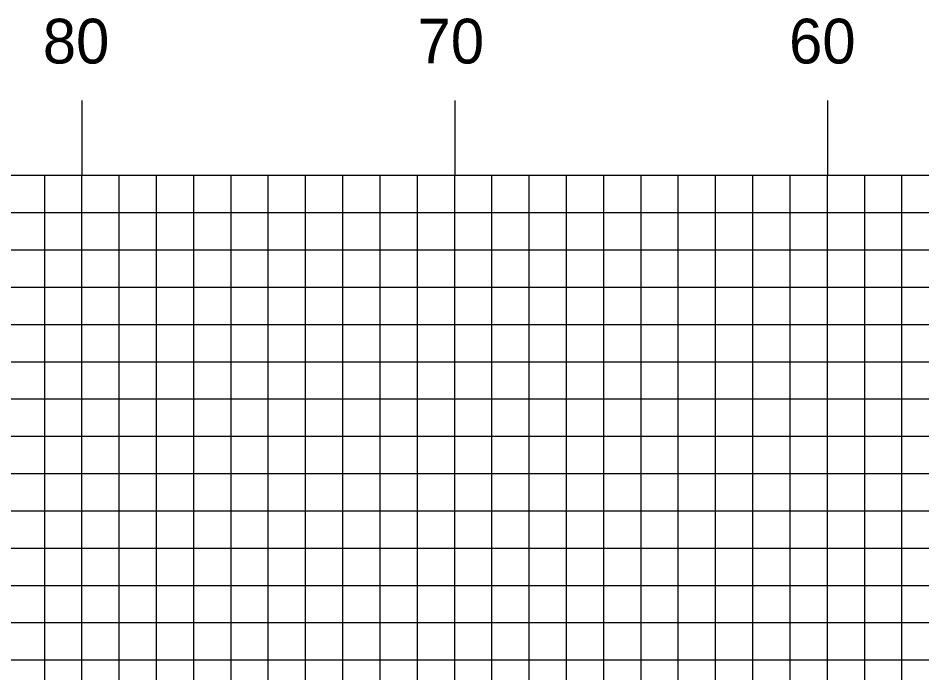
# Model space of a CAD drawing. Extents: x 1789730 to 1790074, y 442591 to 442811.
# Drawn here: x 1789814.47 to 1789838.72, y 442630.32 to 442647.88 of the extents above; entities that cross this region are included whole.
import ezdxf

# ---------------------------------------------------------------- set-up
doc = ezdxf.new("R2010")
doc.units = 0
for name, color, linetype in [('H_V ANNOTATION', 7, 'Continuous'), ('MAJOR', 7, 'Continuous'), ('MINOR', 7, 'Continuous')]:
    doc.layers.add(name, color=color, linetype=linetype)

msp = doc.modelspace()

# ---------------------------------------------------------------- linework, layer by layer
at = {"layer": 'MAJOR'}
for p, q in [((1789816.183, 442645.669), (1789816.183, 442643.665)), ((1789826.183, 442645.669), (1789826.183, 442643.665)), ((1789836.183, 442645.669), (1789836.183, 442643.665)), ((1789756.183, 442643.665), (1790036.183, 442643.665)), ((1789756.183, 442643.665), (1790036.183, 442643.665)), ((1789816.183, 442608.665), (1789816.183, 442643.665)), ((1789826.183, 442608.665), (1789826.183, 442643.665)), ((1789836.183, 442608.665), (1789836.183, 442643.665)), ((1789756.183, 442638.665), (1790036.183, 442638.665)), ((1789756.183, 442633.665), (1790036.183, 442633.665))]:
    msp.add_line(p, q, dxfattribs=at)
at = {"layer": 'MINOR'}
for p, q in [((1789815.183, 442608.665), (1789815.183, 442643.665)), ((1789817.183, 442608.665), (1789817.183, 442643.665)), ((1789818.183, 442608.665), (1789818.183, 442643.665)), ((1789819.183, 442608.665), (1789819.183, 442643.665)), ((1789820.183, 442608.665), (1789820.183, 442643.665)), ((1789821.183, 442608.665), (1789821.183, 442643.665)), ((1789822.183, 442608.665), (1789822.183, 442643.665)), ((1789823.183, 442608.665), (1789823.183, 442643.665)), ((1789824.183, 442608.665), (1789824.183, 442643.665)), ((1789825.183, 442608.665), (1789825.183, 442643.665)), ((1789827.183, 442608.665), (1789827.183, 442643.665)), ((1789828.183, 442608.665), (1789828.183, 442643.665)), ((1789829.183, 442608.665), (1789829.183, 442643.665)), ((1789830.183, 442608.665), (1789830.183, 442643.665)), ((1789831.183, 442608.665), (1789831.183, 442643.665)), ((1789832.183, 442608.665), (1789832.183, 442643.665)), ((1789833.183, 442608.665), (1789833.183, 442643.665)), ((1789834.183, 442608.665), (1789834.183, 442643.665)), ((1789835.183, 442608.665), (1789835.183, 442643.665)), ((1789837.183, 442608.665), (1789837.183, 442643.665)), ((1789838.183, 442608.665), (1789838.183, 442643.665)), ((1789756.183, 442642.665), (1790036.183, 442642.665)), ((1789756.183, 442641.665), (1790036.183, 442641.665)), ((1789756.183, 442640.665), (1790036.183, 442640.665)), ((1789756.183, 442639.665), (1790036.183, 442639.665)), ((1789756.183, 442637.665), (1790036.183, 442637.665)), ((1789756.183, 442636.665), (1790036.183, 442636.665)), ((1789756.183, 442635.665), (1790036.183, 442635.665)), ((1789756.183, 442634.665), (1790036.183, 442634.665)), ((1789756.183, 442632.665), (1790036.183, 442632.665)), ((1789756.183, 442631.665), (1790036.183, 442631.665)), ((1789756.183, 442630.665), (1790036.183, 442630.665))]:
    msp.add_line(p, q, dxfattribs=at)

# ---------------------------------------------------------------- texts
at = {"layer": 'H_V ANNOTATION'}
for s, p in [('80', (1789815.133, 442646.665)), ('70', (1789825.187, 442646.665)), ('60', (1789835.155, 442646.665))]:
    msp.add_text(s, height=1.2, dxfattribs=at).set_placement(p)

doc.saveas('drawing.dxf')
